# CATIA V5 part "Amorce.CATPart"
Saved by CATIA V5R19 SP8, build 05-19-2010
Part number: Amorce
Bounding box of the stored display mesh (mm): x 0 to 3.2, y -3 to 3, z -2.853 to 2.853
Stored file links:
  C:\Users\Arthur\Desktop\Catia parts\Amorce.CATPart
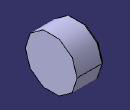
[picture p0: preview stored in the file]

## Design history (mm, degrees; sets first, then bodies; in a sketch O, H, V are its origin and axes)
Set1
  Sketch1 on yz-plane, origin (0, 0, 0), H (0, 1, 0), V (0, 0, 1)
    circle A1 centre (0, 0) radius 3
    radius A1 = 3
Body1 (main body)
  Pad1: profile Sketch1, direction (1, 0, 0), length 3.2
  Chamfer1: length 0.3, angle 45, on edge [start face of Pad1 | face of Pad1 from Sketch1.A1]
